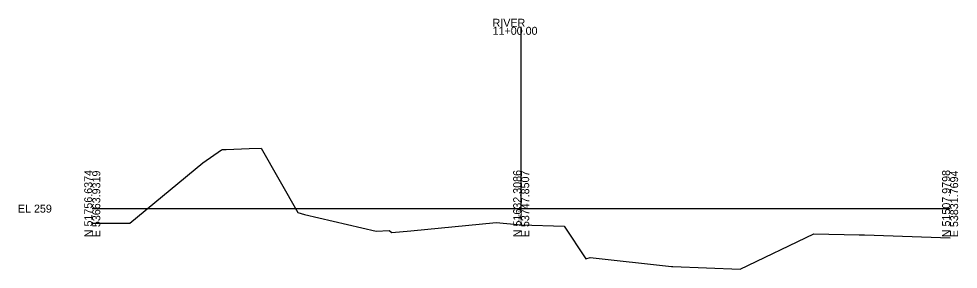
# Model space of a CAD drawing. Extents: x 5628 to 5956, y 92469 to 104012.
# Drawn here: x 5627.6 to 5956.2, y 100457.4 to 100545 of the extents above; entities that cross this region are included whole.
import ezdxf

# ---------------------------------------------------------------- set-up
doc = ezdxf.new("R2010")
doc.units = 0
for name, color, linetype in [('Level 10', 7, 'Continuous'), ('Level 60', 7, 'Continuous'), ('Level 63', 7, 'Continuous')]:
    doc.layers.add(name, color=color, linetype=linetype)

msp = doc.modelspace()

# ---------------------------------------------------------------- linework, layer by layer
at = {"layer": 'Level 60'}
for p, q in [((5692.04, 100494.67), (5698.49, 100499.21)), ((5698.49, 100499.21), (5698.94, 100499.28)), ((5698.94, 100499.28), (5700.13, 100499.28)), ((5700.13, 100499.28), (5708.21, 100499.65)), ((5708.21, 100499.65), (5712.43, 100499.8)), ((5712.43, 100499.8), (5725.28, 100477.21)), ((5666.42, 100473.52), (5692.04, 100494.67)), ((5725.28, 100477.21), (5727.56, 100476.49)), ((5727.56, 100476.49), (5752.64, 100470.72)), ((5653.34, 100473.46), (5666.42, 100473.52)), ((5764.69, 100470.88), (5794.54, 100473.74)), ((5794.54, 100473.74), (5803.34, 100472.91)), ((5803.34, 100472.91), (5818.4, 100472.44)), ((5818.4, 100472.44), (5825.97, 100461.04)), ((5752.64, 100470.72), (5757.22, 100470.93)), ((5757.22, 100470.93), (5758.06, 100470.24)), ((5758.06, 100470.24), (5764.69, 100470.88)), ((5879.92, 100457.4), (5905.67, 100469.84)), ((5905.67, 100469.84), (5921.52, 100469.48)), ((5921.52, 100469.48), (5922.41, 100469.47)), ((5922.41, 100469.47), (5923.36, 100469.4)), ((5923.36, 100469.4), (5953.34, 100468.34)), ((5825.97, 100461.04), (5827.49, 100461.48)), ((5827.49, 100461.48), (5855.95, 100458.34)), ((5855.95, 100458.34), (5856.35, 100458.32)), ((5856.35, 100458.32), (5879.92, 100457.4))]:
    msp.add_line(p, q, dxfattribs=at)
at = {"layer": 'Level 63'}
for p, q in [((5803.34, 100478.6), (5803.34, 100542.22)), ((5653.34, 100478.6), (5803.34, 100478.6)), ((5803.34, 100478.6), (5953.34, 100478.6))]:
    msp.add_line(p, q, dxfattribs=at)

# ---------------------------------------------------------------- texts
at = {"layer": 'Level 10'}
msp.add_text('256.16', height=1.2, rotation=90, dxfattribs=at).set_placement((5803.54, 100473.91))
at = {"layer": 'Level 63'}
for s, p in [('RIVER', (5793.34, 100542.22)), ('11+00.00', (5793.34, 100539.42)), ('EL 259', (5627.33, 100477.2))]:
    msp.add_text(s, height=2.8, dxfattribs=at).set_placement(p)
for s, p in [('N 51756.6374', (5653.34, 100468.6)), ('E 53663.9319', (5656.14, 100468.6)), ('N 51632.3086', (5803.34, 100468.59)), ('E 53747.8507', (5806.14, 100468.6)), ('N 51507.9798', (5953.34, 100468.6)), ('E 53831.7694', (5956.14, 100468.6))]:
    msp.add_text(s, height=2.8, rotation=90, dxfattribs=at).set_placement(p)

doc.saveas('drawing.dxf')
